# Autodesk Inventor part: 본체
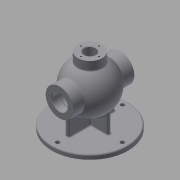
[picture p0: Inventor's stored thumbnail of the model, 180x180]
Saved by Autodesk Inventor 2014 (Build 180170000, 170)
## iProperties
Created: 2020-08
Part Number: 본체
Material: Generic
Document SubType Name: Modeling
Designer: kh
Density: 1 g/cm^3
Appearance: Default
Author: kh
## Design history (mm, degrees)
sketch "Sketch1"
  geometry: C1 r 85 at (0, 0); 1 further point
  constraints: 1 centre point, 1 coincident
  dimensions: "d0" = 170 diameter of C1
extrude "Extrusion1" new body sketch "Sketch1" distance "d1" = 10; taper "d2" = 0 deg
sketch "Sketch2"
  geometry: L1 (85, 10)-(-85, 10) reference; L2 (-85, 0)-(85, 0) reference; L3 (0, 0)-(0, 85); L4 (-68, 85)-(68, 85); L5 (-68, 102.5)-(-52, 102.5); L6 (-52, 102.5)-(-52, 103.5); L7 (-52, 103.5)-(-50.25, 103.5); L8 (-50.25, 103.5)-(-50.25, 102.5); L9 (-50.25, 102.5)-(-39.278, 102.5); L10 (39.278, 102.5)-(68, 102.5); L11 (68, 102.5)-(68, 116); L12 (68, 116)-(42.988, 116); L13 (-42.988, 116)-(-68, 116); L14 (-68, 116)-(-68, 102.5); L15 (68, 85)-(68, 0); A1 r 43 centre (0, 85) between (39.278, 102.5) and (-39.278, 102.5); A2 r 53 centre (0, 85) between (42.988, 116) and (-42.988, 116)
  constraints: 26 end point, 6 perpendicular, 4 collinear, 4 parallel, 4 point on circle, 2 centre point, 2 coincident, 2 point on line, 1 midpoint
  dimensions: "d3" = 85 distance of L3.end L3.start; "d4" = 136 distance of L4.start L4.end; "d5" = 43 radius of A1; "d6" = 16 distance of L5.start L5.end; "d7" = 35 diameter of L10 L4; "d9" = 136 distance between parallel lines of L11 L14; "d10" = 35 diameter of L5 L4; "d11" = 35 diameter of L9 L4; "d12" = 1.75 distance of L6.end L7.end; "d13" = 37 diameter of L7 L4; "d14" = 62 diameter of L12 L4; "d15" = 53 radius of A2
revolve "Revolution1" sketch "Sketch2" stored, may be unused: angle "d16" = 90 deg
sketch "Sketch3" dims "d17" = 48
  geometry: L1 (0, 0)-(0, -24); C1 r 31 at (0, 0) reference; C2 r 17.5 at (0, 0) reference; 1 further point
  constraints: 2 end point, 1 coincident, 1 vertical, 1 vertical alignment, 2 other
hole "Hole1" sketch "Sketch3" at (0, -24) diameter "d18" = 3.242; stored, may be unused: countersink angle "d22" = 90 deg, drill point angle "d24" = 118 deg; dims "d19" = 12, "d20" = 4, "d21" = 2, "d23" = 15
pattern_circular "Circular Pattern1" dims angle "d26" = 360 deg
mirror "Mirror1"
sketch "Sketch4" dims "d28" = 145
  geometry: L1 (0, 0)-(0, -72.5); C1 r 85 at (0, 0) reference; 2 further points
  constraints: 2 coincident, 2 end point, 1 vertical, 1 vertical alignment, 2 other
hole "Hole2" sketch "Sketch4" at (0, -72.5) diameter "d29" = 9; stored, may be unused: countersink angle "d33" = 90 deg, drill point angle "d35" = 0 deg; dims "d30" = 12, "d31" = 4, "d32" = 2, "d34" = 15
pattern_circular "Circular Pattern2" dims angle "d37" = 360 deg
sketch "Sketch6"
  geometry: L1 (85, 10)-(-85, 10) reference; L2 (-85, 0)-(85, 0) reference; L3 (0, 10)-(0, 32); L4 (0, 10)-(52, 10); L5 (42.988, 54)-(68, 54) reference; L6 (52, 10)-(52, 54); A1 r 53 centre (0, 85) between (42.988, 116) and (42.988, 54) reference; 1 further point
  constraints: 6 end point, 2 perpendicular, 2 point on line, 1 midpoint, 1 point on circle
  dimensions: "d40" = 52 distance of L3.start L4.end
feature "Rib1" sketch "Sketch6" dims "d41" = 1, "d42" = 8, "d43" = 0, "d44" = 0, "d45" = 1, "d46" = 1
mirror "Mirror2"
sketch "Sketch7"
  geometry: L1 (85, 10)-(-85, 10) reference; L2 (-85, 0)-(85, 0) reference; L3 (0, 0)-(0, 32.151); L4 (0, 0)-(43, 0); L5 (43, 0)-(43, 54.016); A1 r 53 centre (0, 85) between (4, 32.151) and (-4, 32.151) reference
  constraints: 6 end point, 2 perpendicular, 1 point on circle, 1 point on line
  dimensions: "d47" = 43 distance of L3.start L4.end
feature "Rib2" sketch "Sketch7" dims "d48" = 1, "d49" = 8, "d50" = 0, "d51" = 0, "d52" = 1, "d53" = 1
mirror "Mirror3"
workplane "Work Plane1"
sketch "Sketch8"
  geometry: C1 r 27 at (0, 0); 1 further point
  constraints: 1 centre point, 1 coincident
  dimensions: "d55" = 54 diameter of C1
extrude "Extrusion2" join sketch "Sketch8" stored distance "d56" = 10; taper "d57" = 0 deg
sketch "Sketch9"
  geometry: C1 r 13 at (0, 0); 1 further point
  constraints: 1 centre point, 1 coincident
  dimensions: "d58" = 26 diameter of C1
extrude "Extrusion3" cut sketch "Sketch9" stored distance "d59" = 10; taper "d60" = 0 deg
sketch "Sketch10" dims "d61" = 40
  geometry: L1 (0, 0)-(0, 20); 1 further point
  constraints: 2 end point, 1 coincident, 1 vertical, 1 vertical alignment, 2 other
hole "Hole3" sketch "Sketch10" at (0, 20) diameter "d62" = 3.242; stored, may be unused: countersink angle "d66" = 90 deg, drill point angle "d68" = 118 deg; dims "d63" = 12, "d64" = 4, "d65" = 2, "d67" = 15
pattern_circular "Circular Pattern3" dims angle "d70" = 360 deg
chamfer "Chamfer1" distance "d72" = 1; stored, may be unused: second distance "d73" = 2, angle "d74" = 45 deg
chamfer "Chamfer2" distance "d75" = 1; stored, may be unused: second distance "d76" = 2, angle "d77" = 45 deg
chamfer "Chamfer3" distance "d78" = 1; stored, may be unused: second distance "d79" = 2, angle "d80" = 45 deg
fillet "Fillet1" dims "d81" = 3
fillet "Fillet2" dims "d82" = 3
fillet "Fillet3" dims "d83" = 3
fillet "Fillet4" dims "d84" = 3
fillet "Fillet5" dims "d85" = 3
workplane "Work Plane4"
sketch "Sketch12"
  geometry: L1 (-27, 0)-(27, 0) reference; L2 (-27, -17.714)-(27, -17.714) reference; L3 (0, 0)-(0, -9); L4 (-39.925, -3.221)-(39.925, -3.221); L5 (39.925, -3.221)-(39.925, -14.779); L6 (39.925, -14.779)-(-39.925, -14.779); L7 (-39.925, -14.779)-(-39.925, -3.221); L8 (-39.925, -3.221)-(39.925, -14.779); 1 further point
  constraints: 4 end point, 2 midpoint, 1 perpendicular, 2 other
  dimensions: "d87" = 9 distance of L3.start L3.end
emboss "Emboss1" sketch "Sketch12" dims "d1" = 10, "d3" = 85, "d4" = 136, "d5" = 43, "d6" = 16, "d7" = 35, "d9" = 136, "d10" = 35, "d11" = 35, "d12" = 1.75, "d13" = 37, "d14" = 62, "d15" = 53, "d88" = 0.5, "d89" = 0
body "Solid1"
node "Projected Loop1"
node "Projected Loop2"
node "Projected Loop3"
node "Projected Loop4"
node "Projected Loop5"
node "Projected Loop7"
